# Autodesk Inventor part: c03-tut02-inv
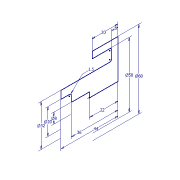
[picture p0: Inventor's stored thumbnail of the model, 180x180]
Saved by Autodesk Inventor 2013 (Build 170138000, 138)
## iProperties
Created: 2010-01
Part Number: c03-tut02-inv
Document SubType Name: Modeling
Designer: CADSoft
Density: 1 g/cm^3
Material: Generic
Author: CADSoft
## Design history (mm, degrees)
sketch "Sketch1"
  geometry: L1 (22, 0)-(22, 30); L2 (22, 30)-(2, 30); L3 (2, 30)-(2, 25); L4 (2, 25)-(15.5, 25); L5 (17, 23.5)-(17, 17.5); L6 (15.5, 16)-(-22, 16); L7 (-22, 16)-(-22, 10); L8 (-22, 10)-(-15.5, 10); L9 (-14, 8.5)-(-14, 4); L10 (-14, 4)-(0, 4); L11 (0, 4)-(0, 0); L12 (0, 0)-(22, 0); A1 r 1.5 centre (-15.5, 8.5) between (-14, 8.5) and (-15.5, 10); A2 r 1.5 centre (15.5, 23.5) between (17, 23.5) and (15.5, 25); A3 r 1.5 centre (15.5, 17.5) between (15.5, 16) and (17, 17.5); 2 further points
  constraints: 24 end point, 6 point on circle, 6 tangent, 3 centre point, 2 coincident, 2 equal radius, 2 vertical, 1 horizontal, 1 other
  dimensions: "d0" = 8 diameter of L10 L12; "d1" = 20 diameter of L8 L12; "d2" = 32 diameter of L6 L12; "d3" = 50 diameter of L4 L12; "d5" = 60 diameter of L2 L12; "d6" = 5 distance between parallel lines of L5 L1; "d7" = 20 distance of L1.end L2.end; "d8" = 22 distance of L11.end L1.start; "d9" = 36 distance between parallel lines of L9 L1; "d10" = 44 distance between parallel lines of L7 L1; "d11" = 1.5 radius of A1
